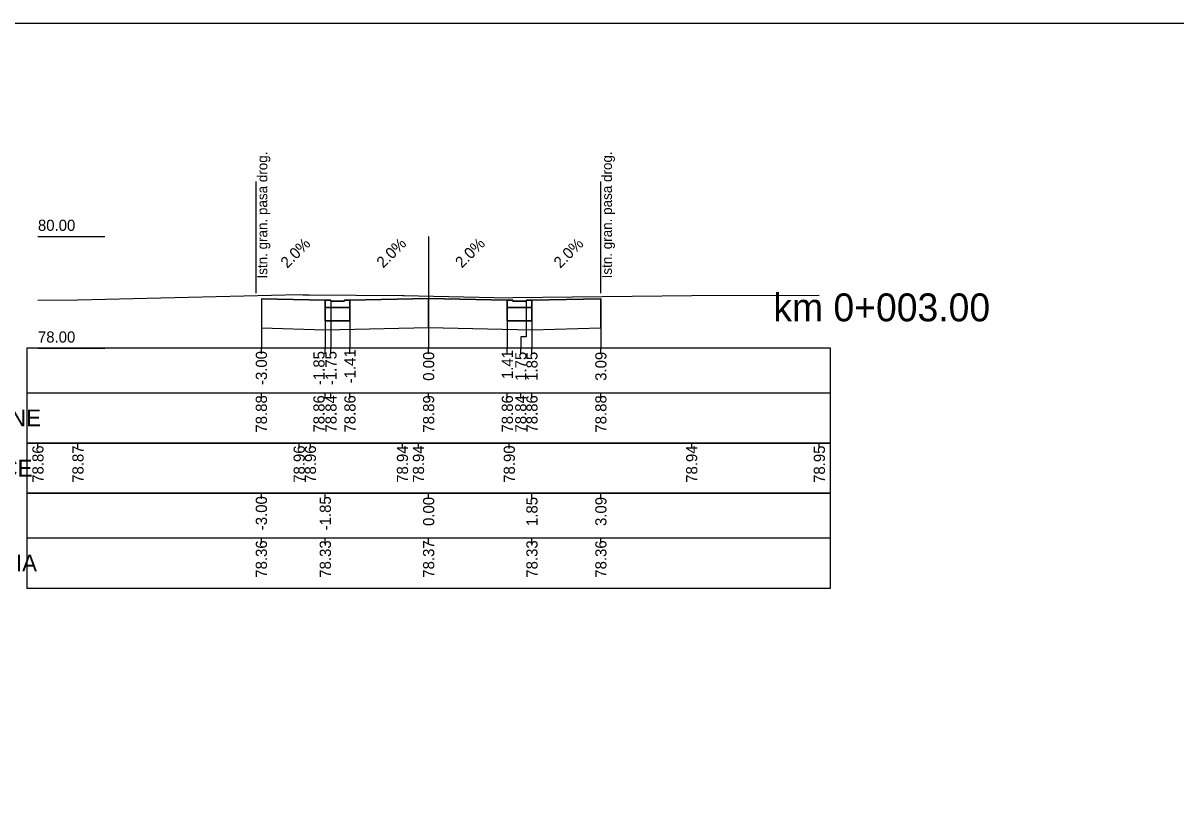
# Model space of a CAD drawing. Extents: x 7492871 to 7493499, y 5802964 to 5802992.
# Drawn here: x 7493052.48 to 7493073.13, y 5802978.08 to 5802992.28 of the extents above; entities that cross this region are included whole.
import ezdxf

# ---------------------------------------------------------------- set-up
doc = ezdxf.new("R2010")
doc.units = 0
for name, color, linetype in [('_wydruk', 7, 'Continuous'), ('opisy_ramki_pop', 7, 'Continuous'), ('pop_comp_kostka', 7, 'Continuous'), ('pop_comp_lawa', 7, 'Continuous'), ('pop_comp_scieralna', 7, 'Continuous'), ('pop_granica_istn', 7, 'Continuous'), ('pop_opis', 7, 'Continuous'), ('pop_os', 7, 'Continuous'), ('pop_pikietaz', 7, 'Continuous'), ('pop_teren', 7, 'Continuous')]:
    doc.layers.add(name, color=color, linetype=linetype)

msp = doc.modelspace()

# ---------------------------------------------------------------- linework, layer by layer
msp.add_lwpolyline([(7493056.746, 5802987.341), (7493057.892, 5802987.318), (7493057.992, 5802987.318), (7493057.993, 5802987.298), (7493058.232, 5802987.298), (7493058.233, 5802987.318), (7493058.333, 5802987.318), (7493059.743, 5802987.346), (7493061.153, 5802987.318), (7493061.253, 5802987.318), (7493061.254, 5802987.298), (7493061.493, 5802987.298), (7493061.494, 5802987.318), (7493061.594, 5802987.318), (7493062.829, 5802987.343)])
at = {"layer": '_wydruk'}
msp.add_lwpolyline([(7492871.369, 5802992.281), (7493499.283, 5802992.281), (7493499.283, 5802963.881), (7492871.369, 5802963.881)], close=True, dxfattribs=at)
at = {"layer": 'opisy_ramki_pop'}
for points in [[(7493056.746, 5802986.821), (7493056.746, 5802986.659), (7493056.746, 5802986.659), (7493056.746, 5802986.459)], [(7493057.892, 5802986.789), (7493057.892, 5802986.659), (7493057.892, 5802986.659), (7493057.892, 5802986.459)], [(7493059.743, 5802986.826), (7493059.743, 5802986.659), (7493059.743, 5802986.659), (7493059.743, 5802986.459)], [(7493061.594, 5802986.789), (7493061.594, 5802986.659), (7493061.594, 5802986.659), (7493061.594, 5802986.459)], [(7493062.829, 5802986.823), (7493062.829, 5802986.659), (7493062.829, 5802986.659), (7493062.829, 5802986.459)]]:
    msp.add_lwpolyline(points, dxfattribs=at)
at = {"layer": 'pop_comp_kostka'}
for p, q in [((7493057.992, 5802987.318), (7493057.892, 5802987.318)), ((7493057.892, 5802987.318), (7493057.892, 5802987.188)), ((7493057.892, 5802987.188), (7493058.333, 5802987.188)), ((7493057.993, 5802987.298), (7493057.992, 5802987.318)), ((7493058.232, 5802987.298), (7493057.993, 5802987.298)), ((7493058.233, 5802987.318), (7493058.232, 5802987.298)), ((7493058.333, 5802987.318), (7493058.233, 5802987.318)), ((7493058.333, 5802987.188), (7493058.333, 5802987.318)), ((7493061.253, 5802987.318), (7493061.153, 5802987.318)), ((7493061.153, 5802987.318), (7493061.153, 5802987.188)), ((7493061.153, 5802987.188), (7493061.594, 5802987.188)), ((7493061.254, 5802987.298), (7493061.253, 5802987.318)), ((7493061.493, 5802987.298), (7493061.254, 5802987.298)), ((7493061.494, 5802987.318), (7493061.493, 5802987.298)), ((7493061.594, 5802987.318), (7493061.494, 5802987.318)), ((7493061.594, 5802987.188), (7493061.594, 5802987.318))]:
    msp.add_line(p, q, dxfattribs=at)
at = {"layer": 'pop_comp_lawa'}
for p, q in [((7493058.333, 5802987.188), (7493057.892, 5802987.188)), ((7493057.892, 5802987.188), (7493057.892, 5802986.948)), ((7493058.333, 5802986.948), (7493058.333, 5802987.188)), ((7493061.594, 5802987.188), (7493061.153, 5802987.188)), ((7493061.153, 5802987.188), (7493061.153, 5802986.948)), ((7493061.594, 5802986.948), (7493061.594, 5802987.188)), ((7493057.892, 5802986.948), (7493058.333, 5802986.948)), ((7493061.153, 5802986.948), (7493061.594, 5802986.948))]:
    msp.add_line(p, q, dxfattribs=at)
at = {"layer": 'pop_comp_scieralna'}
for p, q in [((7493057.892, 5802987.318), (7493056.746, 5802987.341)), ((7493056.746, 5802987.341), (7493056.746, 5802986.821)), ((7493059.743, 5802987.346), (7493058.333, 5802987.318)), ((7493059.743, 5802986.826), (7493059.743, 5802987.346)), ((7493061.153, 5802987.318), (7493059.743, 5802987.346)), ((7493059.743, 5802987.346), (7493059.743, 5802986.826)), ((7493062.829, 5802987.343), (7493061.594, 5802987.318)), ((7493062.829, 5802986.823), (7493062.829, 5802987.343)), ((7493057.892, 5802986.948), (7493057.892, 5802987.318)), ((7493058.333, 5802987.318), (7493058.333, 5802986.948)), ((7493061.153, 5802986.948), (7493061.153, 5802987.318)), ((7493061.594, 5802987.318), (7493061.594, 5802986.948)), ((7493058.333, 5802986.948), (7493057.892, 5802986.948)), ((7493061.594, 5802986.948), (7493061.153, 5802986.948)), ((7493056.746, 5802986.821), (7493057.892, 5802986.789)), ((7493057.892, 5802986.789), (7493059.743, 5802986.826)), ((7493059.743, 5802986.826), (7493061.594, 5802986.789)), ((7493061.594, 5802986.789), (7493062.829, 5802986.823))]:
    msp.add_line(p, q, dxfattribs=at)
at = {"layer": 'pop_granica_istn'}
for p, q in [((7493056.655, 5802987.944), (7493056.655, 5802989.444)), ((7493062.829, 5802987.946), (7493062.829, 5802989.446)), ((7493056.655, 5802987.444), (7493056.655, 5802987.944)), ((7493062.829, 5802987.446), (7493062.829, 5802987.946))]:
    msp.add_line(p, q, dxfattribs=at)
at = {"layer": 'pop_opis'}
for p, q in [((7493052.743, 5802988.459), (7493053.943, 5802988.459)), ((7493052.543, 5802986.459), (7493052.543, 5802984.759)), ((7493052.543, 5802986.459), (7493052.543, 5802984.759)), ((7493052.543, 5802986.459), (7493052.543, 5802984.759)), ((7493052.543, 5802986.459), (7493052.543, 5802984.759)), ((7493052.743, 5802986.459), (7493053.943, 5802986.459)), ((7493056.746, 5802986.359), (7493056.746, 5802986.459)), ((7493057.892, 5802986.359), (7493057.892, 5802986.459)), ((7493057.993, 5802986.359), (7493057.993, 5802986.459)), ((7493058.333, 5802986.359), (7493058.333, 5802986.459)), ((7493059.743, 5802986.359), (7493059.743, 5802986.459)), ((7493061.153, 5802986.359), (7493061.153, 5802986.459)), ((7493061.394, 5802986.359), (7493061.394, 5802986.459)), ((7493061.594, 5802986.359), (7493061.594, 5802986.459)), ((7493062.829, 5802986.359), (7493062.829, 5802986.459)), ((7493052.543, 5802985.659), (7493066.943, 5802985.659)), ((7493052.543, 5802985.659), (7493066.943, 5802985.659)), ((7493052.543, 5802985.659), (7493066.943, 5802985.659)), ((7493052.543, 5802985.659), (7493066.943, 5802985.659)), ((7493056.746, 5802985.559), (7493056.746, 5802985.659)), ((7493057.892, 5802985.559), (7493057.892, 5802985.659)), ((7493057.993, 5802985.559), (7493057.993, 5802985.659)), ((7493058.333, 5802985.559), (7493058.333, 5802985.659)), ((7493059.743, 5802985.559), (7493059.743, 5802985.659)), ((7493061.153, 5802985.559), (7493061.153, 5802985.659)), ((7493061.394, 5802985.559), (7493061.394, 5802985.659)), ((7493061.594, 5802985.559), (7493061.594, 5802985.659)), ((7493062.829, 5802985.559), (7493062.829, 5802985.659)), ((7493052.543, 5802984.759), (7493052.543, 5802983.859)), ((7493052.743, 5802984.659), (7493052.743, 5802984.759)), ((7493053.46, 5802984.659), (7493053.46, 5802984.759)), ((7493057.424, 5802984.659), (7493057.424, 5802984.759)), ((7493057.624, 5802984.659), (7493057.624, 5802984.759)), ((7493059.274, 5802984.659), (7493059.274, 5802984.759)), ((7493059.561, 5802984.659), (7493059.561, 5802984.759)), ((7493061.188, 5802984.659), (7493061.188, 5802984.759)), ((7493064.456, 5802984.659), (7493064.456, 5802984.759)), ((7493066.743, 5802984.659), (7493066.743, 5802984.759)), ((7493052.543, 5802983.859), (7493052.543, 5802982.159)), ((7493056.746, 5802983.759), (7493056.746, 5802983.859)), ((7493057.892, 5802983.759), (7493057.892, 5802983.859)), ((7493059.743, 5802983.759), (7493059.743, 5802983.859)), ((7493061.594, 5802983.759), (7493061.594, 5802983.859)), ((7493062.829, 5802983.759), (7493062.829, 5802983.859)), ((7493052.543, 5802983.059), (7493066.943, 5802983.059)), ((7493056.746, 5802982.959), (7493056.746, 5802983.059)), ((7493057.892, 5802982.959), (7493057.892, 5802983.059)), ((7493059.743, 5802982.959), (7493059.743, 5802983.059)), ((7493061.594, 5802982.959), (7493061.594, 5802983.059)), ((7493062.829, 5802982.959), (7493062.829, 5802983.059))]:
    msp.add_line(p, q, dxfattribs=at)
for points in [[(7493056.746, 5802987.341), (7493056.746, 5802986.659), (7493056.746, 5802986.659), (7493056.746, 5802986.459)], [(7493059.743, 5802987.346), (7493059.743, 5802986.659), (7493059.743, 5802986.659), (7493059.743, 5802986.459)], [(7493062.829, 5802987.343), (7493062.829, 5802986.659), (7493062.829, 5802986.659), (7493062.829, 5802986.459)], [(7493057.892, 5802987.318), (7493057.892, 5802986.659), (7493057.892, 5802986.659), (7493057.892, 5802986.459)], [(7493057.993, 5802987.298), (7493057.993, 5802986.659), (7493057.993, 5802986.659), (7493057.993, 5802986.459)], [(7493058.333, 5802987.318), (7493058.333, 5802986.659), (7493058.333, 5802986.659), (7493058.333, 5802986.459)], [(7493061.153, 5802987.318), (7493061.153, 5802986.659), (7493061.153, 5802986.659), (7493061.153, 5802986.459)], [(7493061.493, 5802987.298), (7493061.493, 5802986.659), (7493061.394, 5802986.659), (7493061.394, 5802986.459)], [(7493061.594, 5802987.318), (7493061.594, 5802986.659), (7493061.594, 5802986.659), (7493061.594, 5802986.459)]]:
    msp.add_lwpolyline(points, dxfattribs=at)
for points in [[(7493052.543, 5802986.459), (7493052.543, 5802984.759), (7493066.943, 5802984.759), (7493066.943, 5802986.459)], [(7493052.543, 5802986.459), (7493052.543, 5802984.759), (7493066.943, 5802984.759), (7493066.943, 5802986.459)], [(7493052.543, 5802986.459), (7493052.543, 5802984.759), (7493066.943, 5802984.759), (7493066.943, 5802986.459)], [(7493052.543, 5802986.459), (7493052.543, 5802984.759), (7493066.943, 5802984.759), (7493066.943, 5802986.459)], [(7493052.543, 5802984.759), (7493052.543, 5802983.859), (7493066.943, 5802983.859), (7493066.943, 5802984.759)], [(7493052.543, 5802983.859), (7493052.543, 5802982.159), (7493066.943, 5802982.159), (7493066.943, 5802983.859)]]:
    msp.add_lwpolyline(points, close=True, dxfattribs=at)
at = {"layer": 'pop_os'}
msp.add_line((7493059.743, 5802988.459), (7493059.743, 5802986.459), dxfattribs=at)
at = {"layer": 'pop_teren'}
msp.add_lwpolyline([(7493052.743, 5802987.318), (7493053.46, 5802987.326), (7493057.424, 5802987.422), (7493057.49, 5802987.416), (7493057.601, 5802987.416), (7493059.274, 5802987.4), (7493059.302, 5802987.401), (7493059.561, 5802987.395), (7493061.188, 5802987.362), (7493061.249, 5802987.363), (7493064.456, 5802987.4), (7493066.743, 5802987.408)], dxfattribs=at)

# ---------------------------------------------------------------- texts
at = {"layer": 'pop_granica_istn'}
for p in [(7493056.853, 5802987.705), (7493063.027, 5802987.708)]:
    msp.add_text('Istn. gran. pasa drog.', height=0.18, rotation=90, dxfattribs=at).set_placement(p)
at = {"layer": 'pop_opis'}
for s, height, p in [('80.00', 0.2, (7493052.743, 5802988.559)), ('78.00', 0.2, (7493052.743, 5802986.559)), ('RZĘDNE PROJEKTOWANE', 0.3, (7493047.671, 5802985.059)), ('RZĘDNE PROJEKTOWANE', 0.3, (7493047.671, 5802985.059)), ('RZĘDNE PROJEKTOWANE', 0.3, (7493047.671, 5802985.059)), ('RZĘDNE PROJEKTOWANE', 0.3, (7493047.671, 5802985.059)), ('RZĘDNE ISTNIEJĄCE', 0.3, (7493048.567, 5802984.159)), ('RZĘDNE KORYTOWANIA', 0.3, (7493047.957, 5802982.459))]:
    msp.add_text(s, height=height, dxfattribs=at).set_placement(p)
for s, rotation, p in [('2.0%', 45, (7493057.21, 5802987.879)), ('2.0%', 45, (7493058.929, 5802987.882)), ('2.0%', 45, (7493060.339, 5802987.882)), ('2.0%', 45, (7493062.103, 5802987.88)), ('-3.00', 90, (7493056.846, 5802985.798)), ('-1.85', 90, (7493057.878, 5802985.796)), ('-1.75', 90, (7493058.093, 5802985.796)), ('-1.41', 90, (7493058.433, 5802985.829)), ('0.00', 90, (7493059.843, 5802985.874)), ('1.41', 90, (7493061.253, 5802985.905)), ('1.75', 90, (7493061.494, 5802985.873)), ('1.85', 90, (7493061.694, 5802985.873)), ('3.09', 90, (7493062.929, 5802985.873)), ('78.88', 90, (7493056.846, 5802984.946)), ('78.86', 90, (7493057.878, 5802984.947)), ('78.84', 90, (7493058.093, 5802984.947)), ('78.86', 90, (7493058.433, 5802984.947)), ('78.89', 90, (7493059.843, 5802984.946)), ('78.86', 90, (7493061.253, 5802984.947)), ('78.84', 90, (7493061.494, 5802984.947)), ('78.86', 90, (7493061.694, 5802984.947)), ('78.88', 90, (7493062.929, 5802984.946)), ('78.86', 90, (7493052.843, 5802984.047)), ('78.87', 90, (7493053.56, 5802984.047)), ('78.96', 90, (7493057.524, 5802984.047)), ('78.96', 90, (7493057.724, 5802984.047)), ('78.94', 90, (7493059.374, 5802984.047)), ('78.94', 90, (7493059.661, 5802984.047)), ('78.90', 90, (7493061.288, 5802984.047)), ('78.94', 90, (7493064.556, 5802984.047)), ('78.95', 90, (7493066.843, 5802984.045)), ('-3.00', 90, (7493056.846, 5802983.198)), ('-1.85', 90, (7493057.992, 5802983.196)), ('0.00', 90, (7493059.843, 5802983.274)), ('1.85', 90, (7493061.694, 5802983.273)), ('3.09', 90, (7493062.929, 5802983.273)), ('78.36', 90, (7493056.846, 5802982.347)), ('78.33', 90, (7493057.992, 5802982.347)), ('78.37', 90, (7493059.843, 5802982.347)), ('78.33', 90, (7493061.694, 5802982.347)), ('78.36', 90, (7493062.929, 5802982.347))]:
    msp.add_text(s, height=0.2, rotation=rotation, dxfattribs=at).set_placement(p)
at = {"layer": 'pop_pikietaz'}
msp.add_text('km 0+003.00', height=0.5, dxfattribs=at).set_placement((7493065.919, 5802986.939))

doc.saveas('drawing.dxf')
